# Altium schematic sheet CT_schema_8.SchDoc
size 278 x 170 mm
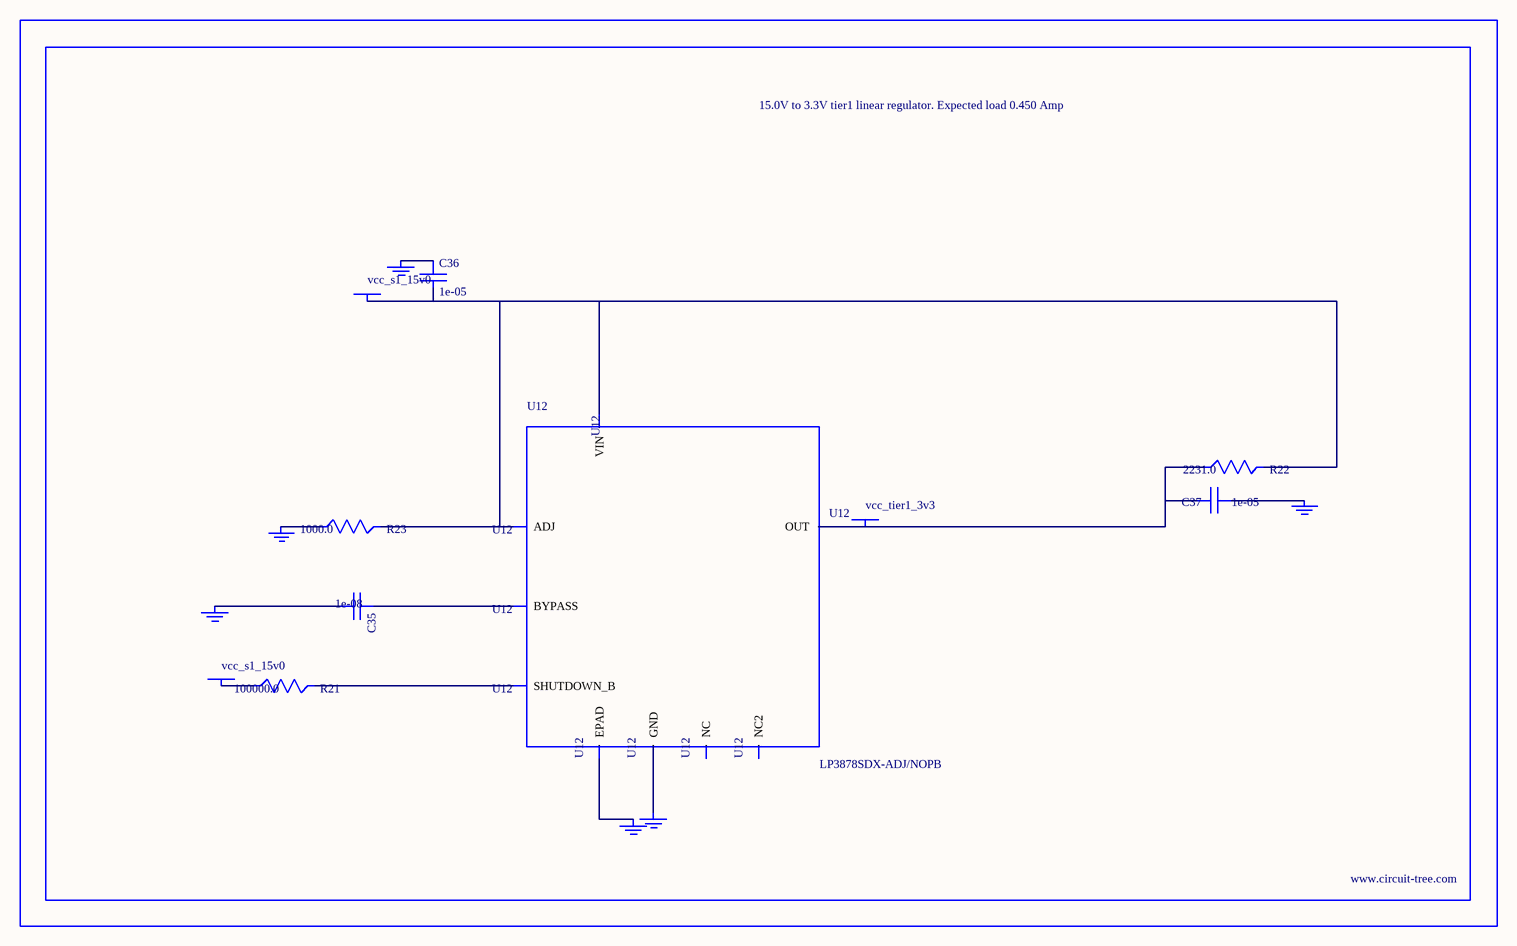
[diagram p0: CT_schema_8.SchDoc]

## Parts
BORDER7  (no value)
C35  1e-08  [C0402]
C36  1e-05  [C1210]
C37  1e-05  [C1210]
GND_INSTANCE_7_0  (no value)
GND_INSTANCE_7_1  (no value)
GND_INSTANCE_7_2  (no value)
GND_INSTANCE_7_3  (no value)
GND_INSTANCE_7_4  (no value)
GND_INSTANCE_7_5  (no value)
POWER_INSTANCE_7_0  vcc_s1_15v0
POWER_INSTANCE_7_1  vcc_s1_15v0
POWER_INSTANCE_7_2  vcc_tier1_3v3
R21  100000.0  [R0603]
R22  2231.0  [R0603]
R23  1000.0  [R0603]
U12  LP3878SDX-ADJ/NOPB  [WSON-8]

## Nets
NetC35_1: C35.1 U12.1(BYPASS)
NetC35_2: C35.2 GND_INSTANCE_7_0.0(GND)
NetC36_1: C36.1 GND_INSTANCE_7_1.0(GND)
NetC36_2: C36.2 POWER_INSTANCE_7_0.0(PWR) R22.2 R23.2 U12.4(VIN) U12.6(ADJ)
NetC37_1: C37.1 GND_INSTANCE_7_2.0(GND)
NetC37_2: C37.2 POWER_INSTANCE_7_2.0(PWR) R22.1 U12.5(OUT)
NetGND_INSTANCE_7_3_0: GND_INSTANCE_7_3.0(GND) R23.1
NetGND_INSTANCE_7_4_0: GND_INSTANCE_7_4.0(GND) U12.PAD(EPAD)
NetGND_INSTANCE_7_5_0: GND_INSTANCE_7_5.0(GND) U12.3(GND)
NetPOWER_INSTANCE_7_1_0: POWER_INSTANCE_7_1.0(PWR) R21.1
NetR21_2: R21.2 U12.8(SHUTDOWN_B)

Not connected (* = marked no-connect by the designer): U12 2(NC) 7(NC2)

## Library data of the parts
BORDER7 = BORDER_PAGE7
C35 = C0402C103K3RAC
C36 = C1210C106K5PACTU
C37 = GRM32DR61E106MA12L
GND_INSTANCE_7_0-GND_INSTANCE_7_5 = GND
POWER_INSTANCE_7_0-POWER_INSTANCE_7_2 = PWR
R21 = RC0603JR-07100KL
R22 = R22
R23 = RC0603JR-071KL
